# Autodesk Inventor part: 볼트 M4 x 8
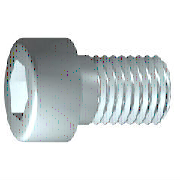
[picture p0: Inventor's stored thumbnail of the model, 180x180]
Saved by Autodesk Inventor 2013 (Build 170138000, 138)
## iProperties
IsCustomPart: 0
Created: 2012-02
Part Number: 볼트 M4 x 8
Material: 스테인리스강
Description: 6각 소켓 머리 캡 나사
Document SubType Name: Modeling
Standard: ISO 4762
Designer: mduedu
Standard Revision: Fourth edition 2004-03-01
Standards Organization: ISO
Language: ko-KR
Size Designation: M4 x 8
Categories: <MemberInstance><Categories><Category DisplayName="조임쇠" InternalName="e4da775c-781d-43d5-af7c-5136215cf5a6" Mnemonic="FSTN"><Category DisplayName="볼트" InternalN
Density: 7.75 g/cm^3
Mass: 1.81382 g
Surface Area: 2.80587 cm^2
Volume: 0.234041 cm^3
Author: mduedu
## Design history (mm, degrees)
sketch "스케치1"
  geometry: L1 (-1, 0)-(8, 0); L2 (8, 0)-(8, 2); L3 (8, 2)-(1.75, 2); L4 (1.75, 2)-(1.32, 2); L5 (1.32, 2)-(0, 2); L6 (0, 2)-(0, 3.5); L7 (0, 3.5)-(-4, 3.5); L8 (-4, 3.5)-(-4, 1.732); L9 (-4, 1.732)-(-2, 1.732); L10 (-2, 1.732)-(-1, 0); L11 (-6.4, 0)-(10.4, 0) reference; L12 (0, -0.7)-(0, 4.2) reference; L13 (1.75, 2)-(0, 2)
  constraints: 22 end point, 6 parallel, 2 collinear, 2 perpendicular, 1 horizontal, 1 point on line
  dimensions: "d1" = 6.25 distance from line of L3.end L2 (= GEL); "d2" = 0.42952 distance of L4.end L3.end (computed from GAL); "d3" = 4 distance between parallel lines of L8 L6 (= KOH); "d4" = 2 distance of L8.end L9.end (= INTI); "d5" = 60 deg angle of L10 L1; "d6" = 4 diameter of L3 L1 (= GD); "d7" = 4 diameter of L5 L1 (= BDM); "d8" = 3.4641 diameter of L9 L1 (= 1.1547 x SW); "d9" = 7 diameter of L7 L1 (= KOD); "d26" = 8 distance between parallel lines of L12 L2 (= NLG)
revolve "본체" sketch "스케치1" stored, may be unused: angle "d10" = 90 deg
sketch "스케치2"
  geometry: L1 (0, -4.9)-(0, 4.9) reference; L2 (-4.9, 0)-(4.9, 0) reference; L3 (1.732, 0)-(0.866, -1.5); L4 (0.866, -1.5)-(-0.866, -1.5); L5 (-0.866, -1.5)-(-1.732, 0); L6 (-1.732, 0)-(-0.866, 1.5); L7 (-0.866, 1.5)-(0.866, 1.5); L8 (0.866, 1.5)-(1.732, 0); 2 further points
  constraints: 12 end point, 1 coincident, 1 horizontal alignment, 1 point on line, 12 other
extrude "슬롯" join sketch "스케치2" stored distance "d11" = 10; taper "d12" = 0 deg
workplane "Work Plane1"
fillet "Fillet2" dims "d30" = 0.1 (= R)
body "Solid1"
fillet "모깎기1" dims "d17" = 0.4 (= RR)
feature "스레드" dims "d13" = 6.25 (= GEL), "d14" = 0
chamfer "모따기1" distance "d15" = 0.42941 (= -0.5 x SPD + 0.5 x GD); stored, may be unused: second distance "d16" = 0.42941 (= GUL), angle "d27" = 45 deg
other parameters: "GD" = 4 [user parameter; used in 2 equation terms], "NLG" = 8 [user parameter; used in 1 equation term], "GEL" = 6.25 [user parameter; used in 2 equation terms], "KOD" = 7 [user parameter; used in 1 equation term], "KOH" = 4 [user parameter; used in 1 equation term], "INTI" = 2 [user parameter; used in 1 equation term], "GAL" = 0.42941 (= 0.61345 x PTC) [user parameter; used in 1 equation term], "GUL" = 0.42941 (= 0.61345 x PTC) [user parameter; used in 1 equation term], "BDM" = 4 (= NND) [user parameter; used in 1 equation term], "SW" = 3 [user parameter; used in 2 equation terms], "RR" = 0.4 [user parameter; used in 1 equation term], "SPD" = 3.14117 (= NND - 1.2269 x PTC) [user parameter; used in 1 equation term], "d19" = 0, "d28" = 0, "d29" = 0, "R" = 0.1 [user parameter; used in 1 equation term], "TOA" = 30 deg [user parameter], "GD1" = 3.14117 (= THREADDIA - 1.2269 x PTC) [user parameter], "THREADDIA" = 4 [user parameter; used in 1 equation term], "FAWI" = 45 deg [user parameter], "TPU" = 14.28571 (computed from PTC) [user parameter], "PTC" = 0.7 [user parameter; used in 5 equation terms], "NND" = 4 [user parameter; used in 2 equation terms], "E0" = 3.465 (= 1.155 x SW) [user parameter]
